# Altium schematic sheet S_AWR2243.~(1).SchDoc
size A3; SheetNumber: 3; SheetTotal: 6; PageSetup: Record=PageOptions¦CenterHorizontal=True¦CenterVertical=True¦PrintScale=1.01¦XCorrection=1.00¦YCorrection=1.00¦PrintKind=1¦BorderSize=5000000¦LeftOffset=0¦BottomOffset=0¦Orientation=2¦PaperLength=1000¦PaperWidth=1000¦Scale=100¦PaperSource=7¦PrintQuality=600¦MediaType=1¦DitherType=10¦PaperKind=A3¦PrintScaleMode=1; SPICEModelCacheFJOGIKSH: <root> / <DocumentId>FJOGIKSH</DocumentId> / <CacheFrame Number="0"> / <Model Name="lmk107b7105_a-t" Kind="CKT"> / <Text>* LMK107B7105_A-T     SPICE MODEL  ( General Type ) / *-------------------------------------------------------------------------------------------------------- / * Model Generated by TAIYO YUDEN Corporation (http://www.ty-top.com) / * Version 1.0 / * TAIYO YUDEN Control No. 170508_100817 / *-------------------------------------------------------------------------------------------------------- / * / * Products Name : Multilayer Ceramic Capacitors / * / * Characteristics : / *     Capacitance : 1 uF , Rated Voltage : 10V , TCC : X7R / *     Case Size : 1.6 x 0.8 / 0.063 x 0.031 [mm/inch] , Thickness : 0.8 / 0.031 [mm/inch] / *     (Conditions: Temperature = 25 degC , DC Bias Current/Voltage = 0A / 0V) / * / * Frequency Range : 40Hz - 3GHz / * / * External Node Assignments : / * / *  1  o---¦ ¦---o  2 / * / *-------------------------------------------------------------------------------------------------------- / .SubCkt LMK107B7105_A-T 1 2 / **************************** / C0 1 110 0.88397u / Cm 1 101 0.082384u / C1 101 102 0.20838u / Rc1 101 102 9.2661k / C2 102 103 0.076898u / Rc2 102 103 586.81 / C3 103 110 0.03072u / Rc3 103 110 23.542 / C2m 1 301 0.075129u / C21 301 302 1.5408u / Rc21 301 302 4.9468k / C22 302 303 0.64532u / Rc22 302 303 9.1693k / C23 303 304 0.76492u / Rc23 303 304 7.2452k / C24 304 305 0.18559u / Rc24 304 305 1.4623k / C25 305 306 0.18363u / Rc25 305 306 1.1324k / C26 306 307 0.074172u / Rc26 306 307 95.555 / C27 307 308 0.089249u / Rc27 307 308 45.035 / C28 308 309 0.054295u / Rc28 308 309 64.279 / C29 309 110 691.04p / Rc29 309 110 17.662 / Rp0 1 110 500Meg / L0 110 120 0.32785n / Lm 120 130 0.17004n / L1 120 121 0.11358n / RL1 121 130 0.3746 / L2 120 122 0.14092n / RL2 122 130 0.22476 / L3 120 123 0.1894n / RL3 123 130 0.27717 / CR 120 124 0.14977u / LR 124 125 0.23899n / RR 125 130 52.409m / CL 130 140 1.8872p / LL 130 140 0.17689n / RL 130 140 42.574 / Rs 140 2 6.0735m / **************************** / .ends</Text> / </Model> / </CacheFrame> / </root>
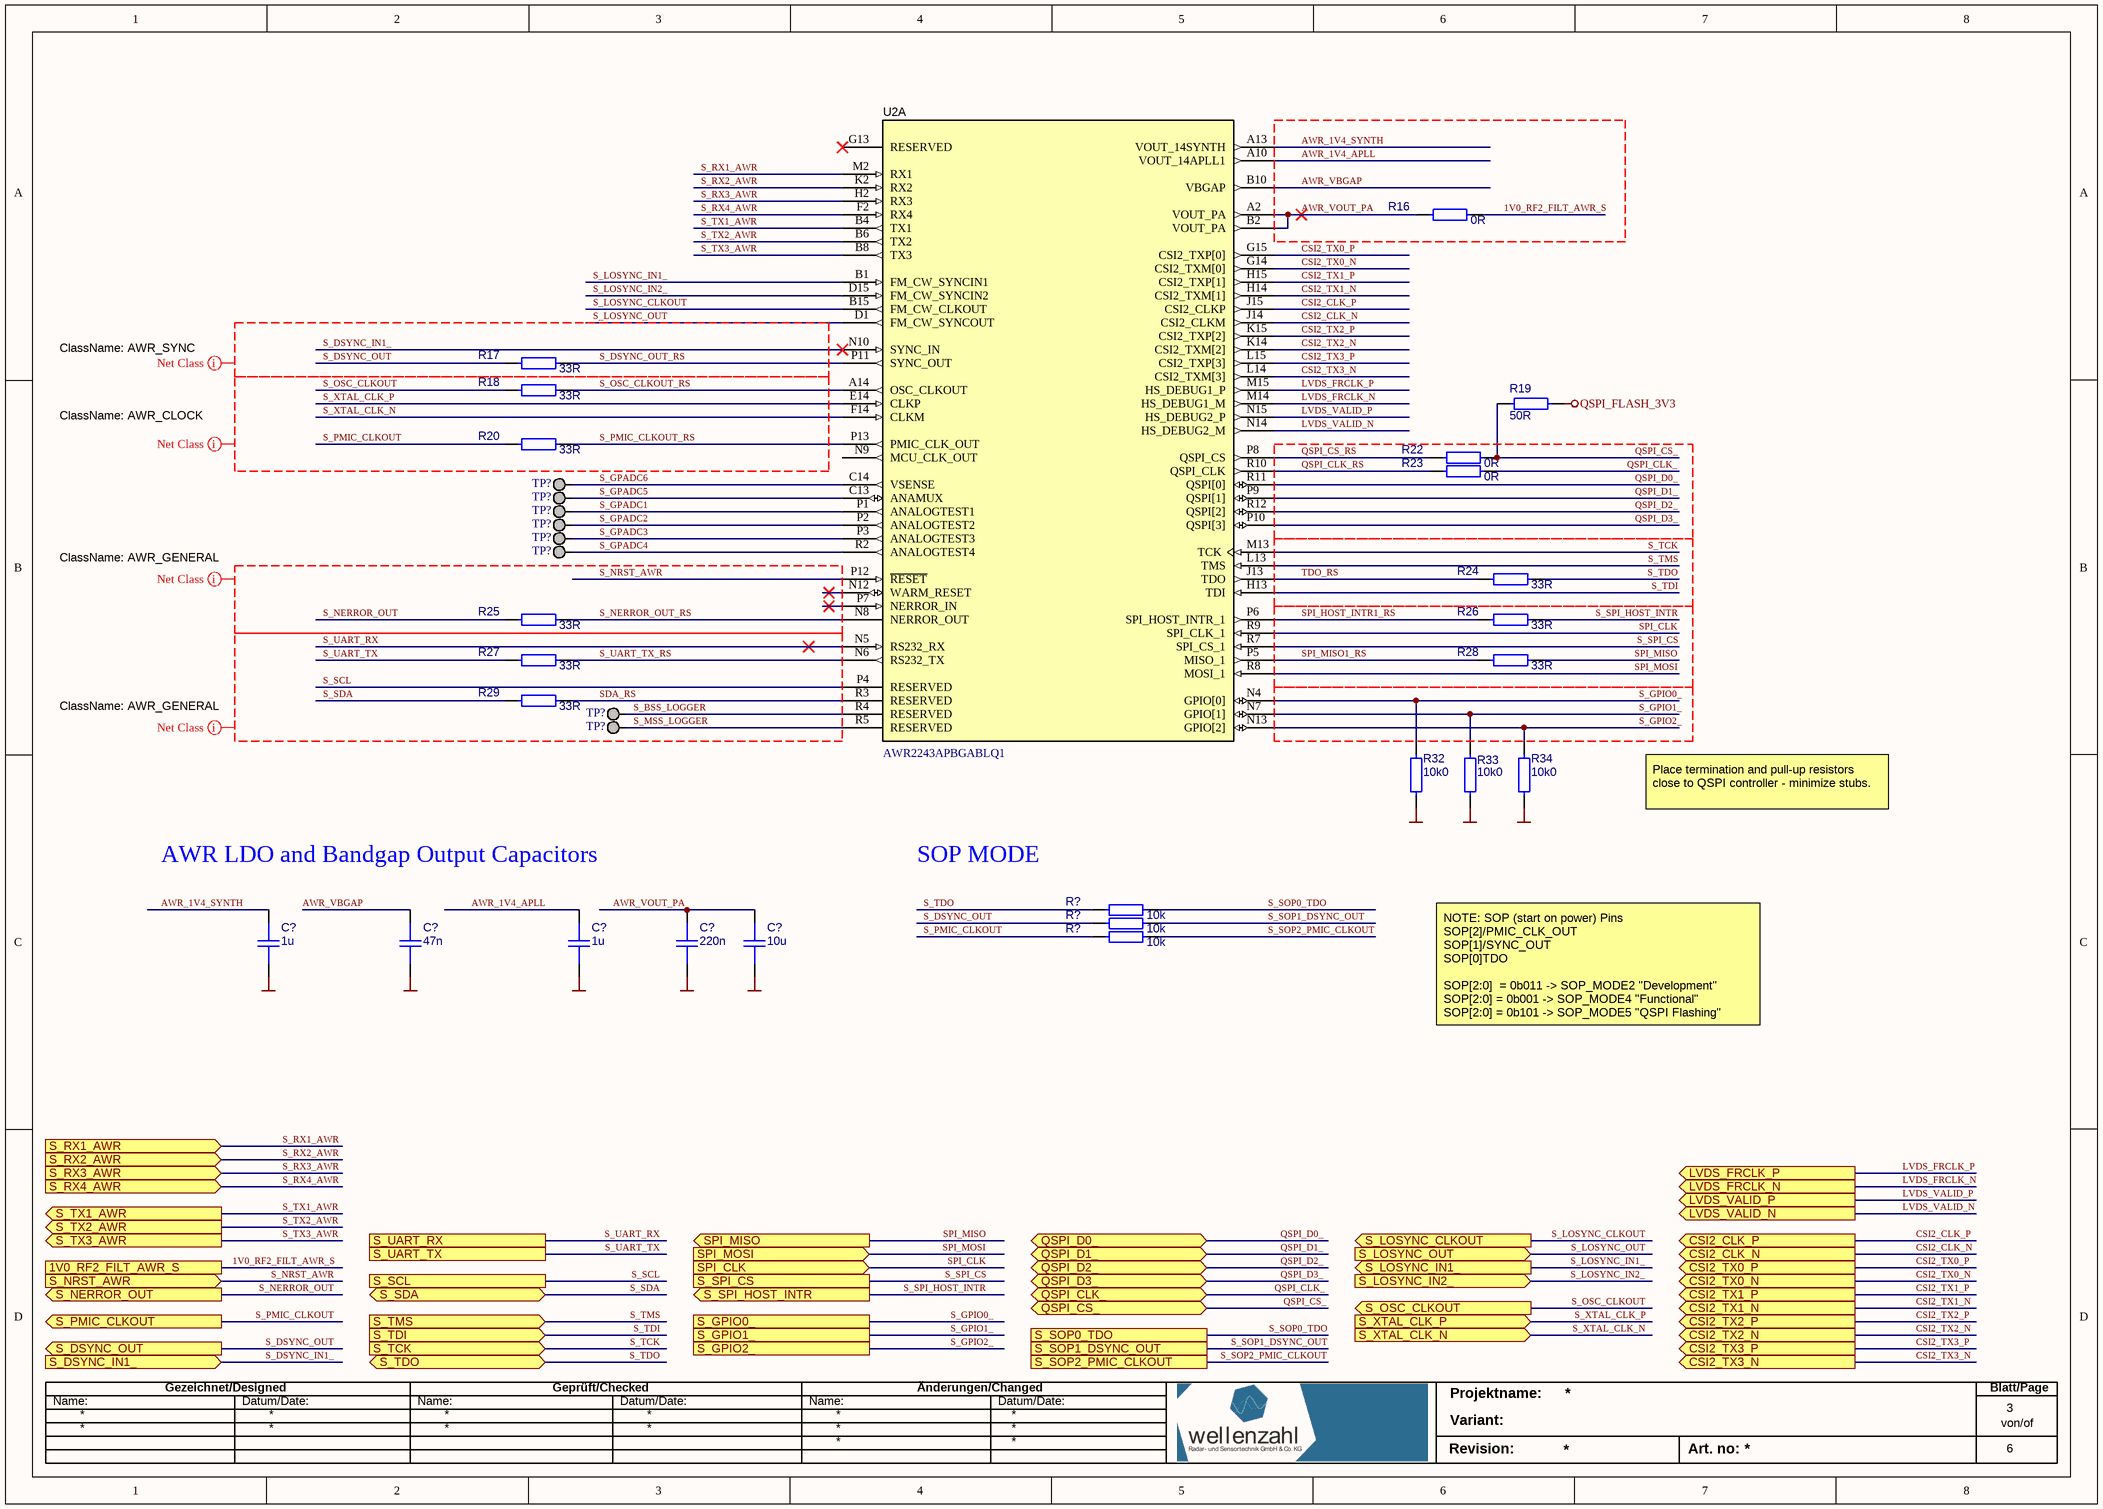
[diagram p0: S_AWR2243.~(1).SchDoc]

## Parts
(Parts that share a designator on the sheet are numbered #1, #2 ... from top to bottom, then left to right.)
C?#1  value 1u  [C0603_M]  (hidden comment: 1uF 0603 X7R 10V 10% WZ)
C?#2  value 47n  [C0402_M]  (hidden comment: 47nF 0402  X7R 25V 10% WZ)
C?#3  value 1u  [C0603_M]  (hidden comment: 1uF 0603 X7R 10V 10% WZ)
C?#4  value 220n  [C0402_M]  (hidden comment: 220nF 0402 X7R 16V 10% WZ)
C?#5  value 10u  [C0805_M]  (hidden comment: 10uF 0805 X7R 10V 10% WZ)
R16  value 0R  [R0402_M]  (hidden comment: 0R Jumper 0402 WZ)
R17  value 33R  [R0402_M]  (hidden comment: 33R 0402 1% 1/16W WZ)
R18  value 33R  [R0402_M]  (hidden comment: 33R 0402 1% 1/16W WZ)
R19  value 50R  [R0402_M]  (hidden comment: 50R 0402 5% 1/16W WZ)
R20  value 33R  [R0402_M]  (hidden comment: 33R 0402 1% 1/16W WZ)
R22  value 0R  [R0402_M]  (hidden comment: 0R Jumper 0402 WZ)
R23  value 0R  [R0402_M]  (hidden comment: 0R Jumper 0402 WZ)
R24  value 33R  [R0402_M]  (hidden comment: 33R 0402 1% 1/16W WZ)
R25  value 33R  [R0402_M]  (hidden comment: 33R 0402 1% 1/16W WZ)
R26  value 33R  [R0402_M]  (hidden comment: 33R 0402 1% 1/16W WZ)
R27  value 33R  [R0402_M]  (hidden comment: 33R 0402 1% 1/16W WZ)
R28  value 33R  [R0402_M]  (hidden comment: 33R 0402 1% 1/16W WZ)
R29  value 33R  [R0402_M]  (hidden comment: 33R 0402 1% 1/16W WZ)
R32  value 10k0  [R0402_M]  (hidden comment: 10k0 0402 5% 1/10W WZ)
R33  value 10k0  [R0402_M]  (hidden comment: 10k0 0402 5% 1/10W WZ)
R34  value 10k0  [R0402_M]  (hidden comment: 10k0 0402 5% 1/10W WZ)
R?#1  value 10k  [R0402_M]  (hidden comment: 10k 0402 5% 1/10W WZ)
R?#2  value 10k  [R0402_M]  (hidden comment: 10k 0402 5% 1/10W WZ)
R?#3  value 10k  [R0402_M]  (hidden comment: 10k 0402 5% 1/10W WZ)
TP?#1  TP_DC_1MM WZ  [TP_DC_1mm]  (value not drawn)
TP?#2  TP_DC_1MM WZ  [TP_DC_1mm]  (value not drawn)
TP?#3  TP_DC_1MM WZ  [TP_DC_1mm]  (value not drawn)
TP?#4  TP_DC_1MM WZ  [TP_DC_1mm]  (value not drawn)
TP?#5  TP_DC_1MM WZ  [TP_DC_1mm]  (value not drawn)
TP?#6  TP_DC_1MM WZ  [TP_DC_1mm]  (value not drawn)
TP?#7  TP_DC_1MM WZ  [TP_DC_1mm]  (value not drawn)
TP?#8  TP_DC_1MM WZ  [TP_DC_1mm]  (value not drawn)
U2  PartNumber: AWR2243APBGABLQ1  [AWR2243_ABL0161A_Footprint]  (hidden comment: AWR2243APBGABLQ1 WZ)  (part A of 2)

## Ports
1V0_RF2_FILT_AWR_S, CSI2_CLK_N (out), CSI2_CLK_P (out), CSI2_TX0_N (out), CSI2_TX0_P (out), CSI2_TX1_N (out), CSI2_TX1_P (out), CSI2_TX2_N (out), CSI2_TX2_P (out), CSI2_TX3_N (out), CSI2_TX3_P (out), LVDS_FRCLK_N (out), LVDS_FRCLK_P (out), LVDS_VALID_N (out), LVDS_VALID_P (out), QSPI_CLK_ (bidir), QSPI_CS_ (bidir), QSPI_D0_ (bidir), QSPI_D1_ (bidir), QSPI_D2_ (bidir), QSPI_D3_ (bidir), S_DSYNC_IN1_ (in), S_DSYNC_OUT (out), S_GPIO0_, S_GPIO1_, S_GPIO2_, S_LOSYNC_CLKOUT (out), S_LOSYNC_IN1_ (out), S_LOSYNC_IN2_ (in), S_LOSYNC_OUT (in), S_NERROR_OUT (out), S_NRST_AWR (in), S_OSC_CLKOUT (out), S_PMIC_CLKOUT (out), S_RX1_AWR (in), S_RX2_AWR (in), S_RX3_AWR (in), S_RX4_AWR (in), S_SCL, S_SDA (bidir), S_SOP0_TDO, S_SOP1_DSYNC_OUT, S_SOP2_PMIC_CLKOUT, S_SPI_CS, S_SPI_HOST_INTR (out), S_TCK (in), S_TDI (in), S_TDO (bidir), S_TMS (in), S_TX1_AWR (out), S_TX2_AWR (out), S_TX3_AWR (out), S_UART_RX, S_UART_TX, S_XTAL_CLK_N (in), S_XTAL_CLK_P (in), SPI_CLK (in), SPI_MISO (out), SPI_MOSI (in)

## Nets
GND: C?#1.1 C?#2.1 C?#3.1 C?#4.1 C?#5.1 R32.1 R33.1 R34.1
QSPI_FLASH_3V3: R19.2
1V0_RF2_FILT_AWR_S: R16.2 ; port 1V0_RF2_FILT_AWR_S
AWR_1V4_APLL: C?#3.2 U2.A10(VOUT_14APLL1)
AWR_1V4_SYNTH: C?#1.2 U2.A13(VOUT_14SYNTH)
AWR_VBGAP: C?#2.2 U2.B10(VBGAP)
AWR_VOUT_PA: C?#4.2 C?#5.2 R16.1 U2.A2(VOUT_PA) U2.B2(VOUT_PA)
CSI2_CLK_N: U2.J14(CSI2_CLKM) ; port CSI2_CLK_N
CSI2_CLK_P: U2.J15(CSI2_CLKP) ; port CSI2_CLK_P
CSI2_TX0_N: U2.G14(CSI2_TXM[0]) ; port CSI2_TX0_N
CSI2_TX0_P: U2.G15(CSI2_TXP[0]) ; port CSI2_TX0_P
CSI2_TX1_N: U2.H14(CSI2_TXM[1]) ; port CSI2_TX1_N
CSI2_TX1_P: U2.H15(CSI2_TXP[1]) ; port CSI2_TX1_P
CSI2_TX2_N: U2.K14(CSI2_TXM[2]) ; port CSI2_TX2_N
CSI2_TX2_P: U2.K15(CSI2_TXP[2]) ; port CSI2_TX2_P
CSI2_TX3_N: U2.L14(CSI2_TXM[3]) ; port CSI2_TX3_N
CSI2_TX3_P: U2.L15(CSI2_TXP[3]) ; port CSI2_TX3_P
LVDS_FRCLK_N: U2.M14(HS_DEBUG1_M) ; port LVDS_FRCLK_N
LVDS_FRCLK_P: U2.M15(HS_DEBUG1_P) ; port LVDS_FRCLK_P
LVDS_VALID_N: U2.N14(HS_DEBUG2_M) ; port LVDS_VALID_N
LVDS_VALID_P: U2.N15(HS_DEBUG2_P) ; port LVDS_VALID_P
QSPI_CLK_: R23.2 ; port QSPI_CLK_
QSPI_CLK_RS: R23.1 U2.R10(QSPI_CLK)
QSPI_CS_: R19.1 R22.2 ; port QSPI_CS_
QSPI_CS_RS: R22.1 U2.P8(QSPI_CS)
QSPI_D0_: U2.R11(QSPI[0]) ; port QSPI_D0_
QSPI_D1_: U2.P9(QSPI[1]) ; port QSPI_D1_
QSPI_D2_: U2.R12(QSPI[2]) ; port QSPI_D2_
QSPI_D3_: U2.P10(QSPI[3]) ; port QSPI_D3_
S_BSS_LOGGER: TP?#7.1 U2.R4(RESERVED)
S_DSYNC_IN1_: U2.N10(SYNC_IN) ; port S_DSYNC_IN1_
S_DSYNC_OUT: R17.1 R?#2.1 ; port S_DSYNC_OUT
S_DSYNC_OUT_RS: R17.2 U2.P11(SYNC_OUT)
S_GPADC1: TP?#3.1 U2.P1(ANALOGTEST1)
S_GPADC2: TP?#4.1 U2.P2(ANALOGTEST2)
S_GPADC3: TP?#5.1 U2.P3(ANALOGTEST3)
S_GPADC4: TP?#6.1 U2.R2(ANALOGTEST4)
S_GPADC5: TP?#2.1 U2.C13(ANAMUX)
S_GPADC6: TP?#1.1 U2.C14(VSENSE)
S_GPIO0_: R32.2 U2.N4(GPIO[0]) ; port S_GPIO0_
S_GPIO1_: R33.2 U2.N7(GPIO[1]) ; port S_GPIO1_
S_GPIO2_: R34.2 U2.N13(GPIO[2]) ; port S_GPIO2_
S_LOSYNC_CLKOUT: U2.B15(FM_CW_CLKOUT) ; port S_LOSYNC_CLKOUT
S_LOSYNC_IN1_: U2.B1(FM_CW_SYNCIN1) ; port S_LOSYNC_IN1_
S_LOSYNC_IN2_: U2.D15(FM_CW_SYNCIN2) ; port S_LOSYNC_IN2_
S_LOSYNC_OUT: U2.D1(FM_CW_SYNCOUT) ; port S_LOSYNC_OUT
S_MSS_LOGGER: TP?#8.1 U2.R5(RESERVED)
S_NERROR_OUT: R25.1 ; port S_NERROR_OUT
S_NERROR_OUT_RS: R25.2 U2.N8(NERROR_OUT)
S_NRST_AWR: U2.P12(~{RESET}) ; port S_NRST_AWR
S_OSC_CLKOUT: R18.1 ; port S_OSC_CLKOUT
S_OSC_CLKOUT_RS: R18.2 U2.A14(OSC_CLKOUT)
S_PMIC_CLKOUT: R20.1 R?#3.1 ; port S_PMIC_CLKOUT
S_PMIC_CLKOUT_RS: R20.2 U2.P13(PMIC_CLK_OUT)
S_RX1_AWR: U2.M2(RX1) ; port S_RX1_AWR
S_RX2_AWR: U2.K2(RX2) ; port S_RX2_AWR
S_RX3_AWR: U2.H2(RX3) ; port S_RX3_AWR
S_RX4_AWR: U2.F2(RX4) ; port S_RX4_AWR
S_SCL: U2.P4(RESERVED) ; port S_SCL
S_SDA: R29.1 ; port S_SDA
S_SOP0_TDO: R?#1.2 ; port S_SOP0_TDO
S_SOP1_DSYNC_OUT: R?#2.2 ; port S_SOP1_DSYNC_OUT
S_SOP2_PMIC_CLKOUT: R?#3.2 ; port S_SOP2_PMIC_CLKOUT
S_SPI_CS: U2.R7(SPI_CS_1) ; port S_SPI_CS
S_SPI_HOST_INTR: R26.2 ; port S_SPI_HOST_INTR
S_TCK: U2.M13(TCK) ; port S_TCK
S_TDI: U2.H13(TDI) ; port S_TDI
S_TDO: R24.2 R?#1.1 ; port S_TDO
S_TMS: U2.L13(TMS) ; port S_TMS
S_TX1_AWR: U2.B4(TX1) ; port S_TX1_AWR
S_TX2_AWR: U2.B6(TX2) ; port S_TX2_AWR
S_TX3_AWR: U2.B8(TX3) ; port S_TX3_AWR
S_UART_RX: U2.N5(RS232_RX) ; port S_UART_RX
S_UART_TX: R27.1 ; port S_UART_TX
S_UART_TX_RS: R27.2 U2.N6(RS232_TX)
S_XTAL_CLK_N: U2.F14(CLKM) ; port S_XTAL_CLK_N
S_XTAL_CLK_P: U2.E14(CLKP) ; port S_XTAL_CLK_P
SDA_RS: R29.2 U2.R3(RESERVED)
SPI_CLK: U2.R9(SPI_CLK_1) ; port SPI_CLK
SPI_HOST_INTR1_RS: R26.1 U2.P6(SPI_HOST_INTR_1)
SPI_MISO: R28.2 ; port SPI_MISO
SPI_MISO1_RS: R28.1 U2.P5(MISO_1)
SPI_MOSI: U2.R8(MOSI_1) ; port SPI_MOSI
TDO_RS: R24.1 U2.J13(TDO)

Not connected (* = marked no-connect by the designer): U2 G13(RESERVED)* N9(MCU_CLK_OUT) N12(WARM_RESET)* P7(NERROR_IN)*

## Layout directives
net class AWR_GENERAL: S_BSS_LOGGER, S_MSS_LOGGER, S_NERROR_OUT, S_NERROR_OUT_RS, S_NRST_AWR, S_SCL, S_SDA, S_UART_RX, S_UART_TX, S_UART_TX_RS, SDA_RS
net class AWR_CLOCK: S_OSC_CLKOUT, S_OSC_CLKOUT_RS, S_PMIC_CLKOUT, S_PMIC_CLKOUT_RS, S_XTAL_CLK_N, S_XTAL_CLK_P
net class AWR_SYNC: S_DSYNC_IN1_, S_DSYNC_OUT, S_DSYNC_OUT_RS, S_LOSYNC_OUT

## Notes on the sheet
- Place termination and pull-up resistors close to QSPI controller - minimize stubs.
- AWR LDO and Bandgap Output Capacitors
- SOP MODE
- NOTE: SOP (start on power) Pins SOP[2]/PMIC_CLK_OUT
  SOP[1]/SYNC_OUT
  SOP[0]TDO
  SOP[2:0]  = 0b011 -> SOP_MODE2 "Development"
  SOP[2:0]	= 0b001 -> SOP_MODE4 "Functional"
  SOP[2:0]	= 0b101 -> SOP_MODE5 "QSPI Flashing"

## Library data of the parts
C?#1 C?#3 = CMP-001-00155-1: 0603 1 uF 10 V ±10% Tolerance X7R SMT Multilayer Ceramic Capacitor; Barcode: 000351; Assembly: SMD
C?#2 = CMP-001-00112-1: Cap, 0.047ΜF, 25V, 10%, X7R, 0402; Barcode: 000127; Assembly: SMD
C?#4 = CMP-001-00110-1: 0402 0.22 uF 16 V ±10 % Tolerance X7R SMT Multilayer Ceramic Capacitor; Barcode: 000579; Assembly: SMD
C?#5 = CMP-001-00090-3: Kondensator aus mehreren Keramikschichten MLCC - SMD/SMT 0805 10uF 10volts X7R 10%; BarcodePKTec: 020000000178; Barcode: 000581; Assembly: SMD
R16 R22 R23 = CMP-009-00192-3: Zero-Ohm-Resistor: Rmax. = 20 m, Imax. = 1.5 A; Assembly: SMD; Barcode: 000307; BarcodePKTec: 020000000211; Power Rating: 1.5A
R17 R18 R20 R24-R29 = CMP-009-00303-2: Surface Mount Thick Film Resistor, AEC-Q200 ERJ Series, 33 ohm, 100mW, - 1%; Assembly: SMD; Power Rating: 63mW; Barcode: 000000
R19 = CMP-009-00182-5: RES SMD 50 OHM 5% 1/16W 0402; Barcode: 000567
R32-R34 = CMP-009-00193-3: Dickfilmwiderstände - SMD 0402 10Kohms 5% AEC-Q200; Barcode: 000058; BarcodePKTec: 020000000206
R?#1-R?#3 = CMP-009-00193-5: Dickfilmwiderstände - SMD 0402 10Kohms 5% AEC-Q200; Barcode: 000058; BarcodePKTec: 020000000206
TP?#1-TP?#8 = CMP-00030-3: DC, 1mm Test Point, SMT; Barcode: 999999
U2 = CMP-096-000000-4: Single Chip 77 and 79 GHz FMCW Transceiver, ABL0161A (FCBGA-161); Manufacturer: Texas Instruments; Rating: Automotive; CompType: IC; AEC Category: Q200; SizeArea_mm2: 108.16; SizeAreaWB_mm2: 153.76; SizeZ_mm: 1.17; SizeY_mm: 10.4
